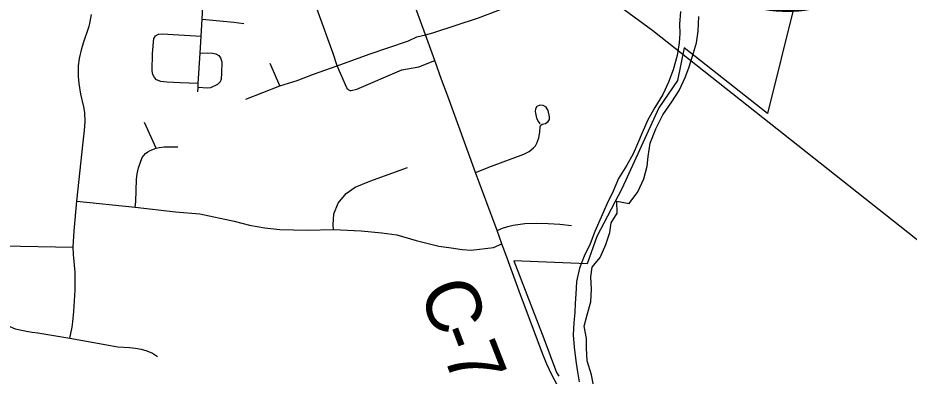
# Model space of a CAD drawing. Extents: x 114604 to 551442, y 316898 to 567001.
# Drawn here: x 129780 to 134680, y 436168 to 438138 of the extents above; entities that cross this region are included whole.
import ezdxf

# ---------------------------------------------------------------- set-up
doc = ezdxf.new("R2010")
doc.units = 0
for name, color, linetype in [('DV_X_County_Line', 7, 'Continuous'), ('GE_P_Alignment_1000_Bearings', 7, 'Continuous'), ('GE_P_Alignment_100_Cardinal_Points', 7, 'Continuous'), ('GE_P_Alignment_100_Distances', 7, 'Continuous'), ('GE_P_Alignment_100_Stations', 7, 'Continuous'), ('GE_P_Alignment_500_Bearings', 7, 'Continuous'), ('PM_P_CL_Double_Solid', 7, 'Continuous')]:
    doc.layers.add(name, color=color, linetype=linetype)

msp = doc.modelspace()

# ---------------------------------------------------------------- linework, layer by layer
at = {"layer": 'DV_X_County_Line'}
for points in [[(133421.9, 438173.5), (133417.6, 438103.3), (133419.4, 438051.2), (133415.2, 438001.1), (133404.9, 437931), (133382.5, 437852.9), (133356.2, 437784.8), (133325.9, 437716.7), (133281.5, 437644.7), (133243.2, 437576.7), (133212.8, 437506.6), (133186.5, 437444.6), (133162.3, 437390.5), (133128, 437328.5), (133081.6, 437254.5), (133053.3, 437184.4), (133016.9, 437114.4), (132986.6, 437042.3), (132952.2, 436964.2), (132925.9, 436896.1), (132893.5, 436828.1), (132867.2, 436762), (132850.9, 436687.9), (132846.6, 436619.7), (132844.4, 436569.6), (132842.2, 436517.5), (132835.9, 436463.4), (132833.6, 436395.3), (132837.4, 436327.1), (132847.1, 436252.9), (132854.9, 436202.7), (132866.6, 436136.5)], [(132946.7, 436108.2), (132932.9, 436176.4), (132909.2, 436252.6), (132905.5, 436322.8), (132905.7, 436374.9), (132893.9, 436443.2), (132910.2, 436505.2), (132930.6, 436577.4), (132932.9, 436647.5), (132929.1, 436713.7), (132937.4, 436767.8), (132981.6, 436819.8), (133012, 436891.8), (133034.3, 436957.9), (133042.5, 437012), (133074.8, 437064), (133073.1, 437130.2), (133141.1, 437117.9), (133187.5, 437181.9), (133221.8, 437254), (133240.1, 437322.1), (133244.3, 437376.2), (133256.7, 437448.3), (133287, 437528.4), (133325.4, 437604.5), (133375.8, 437676.5), (133416.1, 437738.5), (133448.5, 437810.5), (133468.7, 437862.6), (133489, 437926.7), (133511.3, 438000.8), (133519.6, 438064.9), (133524, 438145.1)]]:
    msp.add_lwpolyline(points, dxfattribs=at)
at = {"layer": 'GE_P_Alignment_1000_Bearings'}
msp.add_lwpolyline([(128478.6, 440489.4), (130998.1, 439417.9), (131779.8, 439072.5), (132352.2, 438743.3), (133270.1, 438068.7), (136073.7, 435851.8), (137428.7, 434712.6), (140276.2, 432131.7), (143769.3, 428946.1), (146519.3, 426434.1), (147203, 425812.1)], dxfattribs=at)
at = {"layer": 'GE_P_Alignment_100_Cardinal_Points'}
for p, q in [((131219.3, 437764.1), (131166.5, 437887.7)), ((130539.9, 437421.5), (130475.5, 437562))]:
    msp.add_line(p, q, dxfattribs=at)
for points in [[(131605.6, 437738.7), (131600.2, 437740.5), (131594.5, 437745.9), (131589.3, 437753.8), (131535.3, 437873.4), (131512.5, 437942.1), (131430.5, 438169.5), (131379.9, 438309.9), (131326, 438452.4), (131235.2, 438707.1), (131222.1, 438736.4), (131212.7, 438767.2), (131207, 438799), (131217.8, 438883.9), (131251.6, 439343.4), (131276.1, 439653.8), (131289.2, 439816.3), (131292, 440035.2)], [(130769, 437731.1), (130770.4, 437754.4), (130771.7, 437777), (130781.7, 437944.8), (130787.6, 438036.6), (130792.6, 438131.1), (130808.9, 438444.4)], [(132020.3, 438045.1), (132061.6, 438055.5), (132311.9, 438138.6), (132419.3, 438178.4), (132539.3, 438229.5), (132603, 438251.3), (132814, 438341.3)], [(130066, 436377.4), (130078.5, 436437.4), (130082.8, 436466.3), (130088.3, 436524.5), (130095.7, 436641), (130095, 436739.3), (130086.6, 436837), (130084.8, 436878.1), (130089.4, 436967.4), (130105, 437129.9), (130138.5, 437454.6), (130146.4, 437519.4), (130149.5, 437567.6), (130147.5, 437617.1), (130142.2, 437649.3), (130126.3, 437717.8), (130116.6, 437776.8), (130112.9, 437816.2), (130113.9, 437874), (130118.9, 437915.5), (130131.5, 437969.7), (130140.4, 438000.9), (130172.9, 438092.5), (130176.2, 438106.2), (130185.1, 438156)], [(130792.6, 438131.1), (130967.1, 438114.3), (131021.8, 438107.4)], [(130771.7, 437777), (130672.9, 437780.4), (130599.9, 437784.8), (130565.9, 437788.2), (130542.7, 437796.5), (130530.5, 437811), (130521.9, 437826.7), (130518.1, 437846.2), (130521, 437942.2), (130527.7, 438024.9), (130537.4, 438039.5), (130553.1, 438048.2), (130572.5, 438049.5), (130787.6, 438036.6)], [(131033.9, 437690.9), (131219.3, 437764.1), (131315, 437794.4), (131406.1, 437828.8), (131535.3, 437873.4), (131711.7, 437939.1), (131927.1, 438012.6), (131973.9, 438033.4), (132020.3, 438045.1)], [(130781.7, 437944.8), (130821, 437945.1), (130849.2, 437943.3), (130868.6, 437939.8), (130884.5, 437930.2), (130894.3, 437918.1), (130901.8, 437896.3), (130899.3, 437833.5), (130897.1, 437801.5), (130892.8, 437785.7), (130878.4, 437771), (130838.4, 437753.7), (130820.8, 437750.9), (130770.4, 437754.4)], [(131605.6, 437738.7), (131611.6, 437738.6), (131643.6, 437745.5), (131890.3, 437853.1), (131984.6, 437869.5), (132071.5, 437903.3)], [(132296.2, 437288.5), (132384.7, 437322.9), (132562, 437388.6), (132590.5, 437403.1), (132615.2, 437422.9), (132625.4, 437435), (132633.6, 437448.3), (132644.7, 437478), (132649.5, 437509.6), (132651.3, 437538.1), (132655.9, 437548.1), (132662.8, 437554.2), (132680.3, 437558), (132694.8, 437567.6), (132702.8, 437579.3), (132703.4, 437593.9), (132694.4, 437628.1), (132684.1, 437646.3), (132668.7, 437656.4), (132650.4, 437657.7), (132633.7, 437650.3), (132626.5, 437638.6), (132623.7, 437622.5), (132631.2, 437586.8), (132641.6, 437567.2), (132650.4, 437554.9)], [(130425, 437097.8), (130428.3, 437127.8), (130432.3, 437250.3), (130435.9, 437281), (130443.1, 437313.9), (130464.1, 437370.3), (130482.5, 437392.6), (130494.9, 437401.9), (130508, 437409.2), (130539.9, 437421.5), (130556.7, 437425.5), (130585.2, 437428.1), (130659.8, 437428.7)], [(131515.5, 436974.3), (131513, 436999.7), (131517.7, 437061), (131540.7, 437119.7), (131584.2, 437172.7), (131633.8, 437208.2), (131715.5, 437240.9), (131922.7, 437315.6)], [(130105, 437129.9), (130425, 437097.8), (130647.5, 437071.3), (130780, 437061.6), (130970, 437019.7), (131053.2, 436998.1), (131137.6, 436982.9), (131221, 436974.6), (131370.4, 436970.1), (131515.5, 436974.3), (131667.1, 436967.5), (131781.3, 436956.4), (131862.7, 436944.5), (131968.8, 436913.9), (132094.4, 436883.5), (132161.8, 436872.9), (132221.9, 436865.4), (132272.5, 436861.1), (132394.1, 436875.8), (132441.1, 436896.6)], [(132414.1, 436969.7), (132443.5, 436982.1), (132473.5, 436991.8), (132503.7, 436998.9), (132567.9, 437007), (132631.9, 437008.8), (132696, 437007.7), (132760, 437003.2), (132824.2, 436996.6)], [(128955.7, 436827.1), (128993.1, 436853.6), (129032.2, 436871.9), (129072.6, 436884.9), (129095.6, 436890), (129130, 436894.6), (129171.4, 436895.7), (129388.4, 436882.8), (129584.8, 436882.9), (129696.8, 436884.6), (130084.8, 436878.1)], [(129696.8, 436884.6), (129695.9, 436780), (129691.3, 436618.3), (129692.1, 436586), (129689.7, 436553.8), (129690.5, 436521.4), (129698.1, 436490.1), (129712.9, 436461.7), (129736, 436440.5), (129765.8, 436427.7), (129827.4, 436414.8), (129858.1, 436409.9), (129889.6, 436407), (130066, 436377.4), (130330.4, 436330.3), (130393.8, 436326.2), (130426.5, 436322.5), (130458.5, 436316.5), (130489.7, 436307.2), (130519.4, 436294), (130547.2, 436276.5)]]:
    msp.add_lwpolyline(points, dxfattribs=at)
at = {"layer": 'GE_P_Alignment_100_Stations'}
msp.add_lwpolyline([(134785.4, 438984.2), (134128.4, 438529), (133901.8, 437611.9), (133442.1, 437973.9), (133405.4, 437794.3), (133303.5, 437643.3), (133099.8, 437198.2), (132962.4, 436936.5), (132909, 436785.9), (132506.8, 436802.2), (132670.8, 436374.9), (132742, 436189.3), (132753.3, 436167.7)], dxfattribs=at)
at = {"layer": 'GE_P_Alignment_500_Bearings'}
for p, q in [((132020.3, 438045.1), (131913.8, 438338.9)), ((132071.5, 437903.3), (132020.3, 438045.1)), ((132414.1, 436969.7), (132296.2, 437288.5)), ((132441.1, 436896.6), (132414.1, 436969.7))]:
    msp.add_line(p, q, dxfattribs=at)
for points in [[(132296.2, 437288.5), (132144, 437708.1), (132108.2, 437799.2), (132071.5, 437903.3)], [(132477.2, 436796.6), (132475.4, 436801.5), (132441.1, 436896.6)], [(132664.9, 436292.5), (132536, 436635.3), (132477.2, 436796.6)], [(132752.1, 436108.4), (132749.2, 436113.3), (132714.1, 436179.6), (132688.1, 436234.9), (132664.9, 436292.5)]]:
    msp.add_lwpolyline(points, dxfattribs=at)

# ---------------------------------------------------------------- texts
at = {"layer": 'GE_P_Alignment_100_Distances'}
msp.add_text('MADISON COUNTY', height=1000.028, rotation=358.4409, dxfattribs=at).set_placement((130198.2, 438288.1))
at = {"layer": 'PM_P_CL_Double_Solid'}
for s, rotation, p in [('C', 289.3523, (131984.8, 436646)), ('-', 290.9501, (132069.6, 436405)), ('7', 291.4015, (132114.6, 436287.5))]:
    msp.add_text(s, height=300, rotation=rotation, dxfattribs=at).set_placement(p)

doc.saveas('drawing.dxf')
